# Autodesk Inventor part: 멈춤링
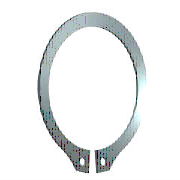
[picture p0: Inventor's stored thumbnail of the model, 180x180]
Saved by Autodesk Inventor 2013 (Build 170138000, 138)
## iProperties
IsCustomPart: 0
Created: 2009-02
Part Number: 멈춤링
Material: 강, 연강
Description: 리테이닝 링(C형)
Document SubType Name: Modeling
Standard: KS B 1336
Designer: KYOUNG IL JANG
Standards Organization: KS
Language: ko-KR
Size Designation: 22 x 1.2
Categories: <MemberInstance><Categories><Category DisplayName="샤프트 부품" InternalName="7f7aeb1f-a693-4053-b835-cee3144e0d98" Mnemonic="SHFT"><Category DisplayName="써클립" Inter
Density: 7.86 g/cm^3
Mass: 1.82859 g
Surface Area: 5.91219 cm^2
Volume: 0.232645 cm^3
Author: KYOUNG IL JANG
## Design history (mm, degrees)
sketch "스케치1"
  geometry: L1 (-6, 0)-(6, 0) reference; L2 (0, 20.189)-(0, -80.536) reference; L3 (-48.09, 0)-(48.09, 0) reference; L4 (-0.5, -21.488)-(-0.5, -25.588); L5 (-0.5, -6.54)-(-0.5, -13.29); L6 (-2.795, 2.7)-(3.672, 2.7); L7 (0.5, -6.54)-(0.5, -13.29); L8 (0.5, -21.488)-(0.5, -25.588); C1 r 1 at (-2, -23.437); C2 r 1 at (2, -23.437); A1 r 10.5 centre (0, -11) between (0.5, -21.488) and (-0.5, -21.488); A2 r 13.025 centre (0, -10.325) between (5.149, -22.289) and (-5.149, -22.289); A3 r 14.597 centre (0, -11) between (-2.318, -25.411) and (-0.5, -25.588); A4 r 2 centre (-2, -23.437) between (-3.97, -23.781) and (-2.318, -25.411); A5 r 2 centre (-5.94, -24.126) between (-3.97, -23.781) and (-5.149, -22.289); A6 r 2 centre (5.94, -24.126) between (5.149, -22.289) and (3.97, -23.781); A7 r 2 centre (2, -23.437) between (2.318, -25.411) and (3.97, -23.781); A8 r 14.597 centre (0, -11) between (0.5, -25.588) and (2.318, -25.411)
  constraints: 16 point on circle, 12 end point, 10 centre point, 9 symmetric about line, 5 point on line, 4 tangent, 3 coincident, 2 horizontal, 1 perpendicular, 1 vertical, 5 other
  dimensions: "d0" = 21 diameter of A1 (= ND); "d1" = 4.1 distance of L4.end L4.start (= SRB2); "d6" = 0.5 distance between parallel lines of L2 L5 (= 0.25 x SD5); "d7" = 2.7 distance between parallel lines of L6 L3 (= SRB1); "d8" = 0.675 distance of A1.centre A2.centre (= 0.25 x SRB1); "d9" = 2 radius of A4 (= SD5); "d10" = 2 radius of A5 (= SD5); "d11" = 1.5 distance from line of L4 A4.centre (= 0.75 x SD5); "d12" = 2 diameter of C1 (= SD5); "d13" = 2 diameter of C2 (= SD5); "d14" = 11 distance from line of A1.centre L1 (= 0.5 x WD)
extrude "본체" new body sketch "스케치1" distance "d2" = 1.2 (= SD); taper "d3" = 0 deg
workaxis "Work Axis1"
workplane "Work Plane1"
body "Solid1"
other parameters: "WD" = 22 (= WDMIN) [user parameter; used in 1 equation term], "SD" = 1.2 [user parameter; used in 1 equation term], "SRB1" = 2.7 [user parameter; used in 2 equation terms], "ND" = 21 [user parameter; used in 1 equation term], "SRB2" = 4.1 [user parameter; used in 1 equation term], "SD5" = 2 [user parameter; used in 6 equation terms], "d15" = 0, "d16" = 0, "d17" = 0, "d41" = 0, "d42" = 0, "WDMIN" = 22 [user parameter; used in 1 equation term], "SD3" = 20.5 [user parameter], "WDMAX" = 24 [user parameter]
